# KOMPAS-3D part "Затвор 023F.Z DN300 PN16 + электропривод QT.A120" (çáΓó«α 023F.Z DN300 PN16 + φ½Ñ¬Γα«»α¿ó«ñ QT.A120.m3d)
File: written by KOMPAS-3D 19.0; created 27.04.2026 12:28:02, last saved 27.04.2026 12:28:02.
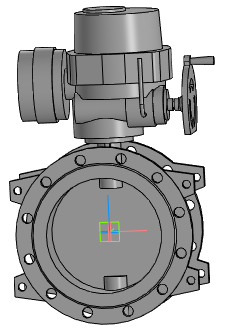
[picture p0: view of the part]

Document properties: Полное имя файла: Затвор 023F.Z DN300 PN16 + электропривод QT.A120.a3d

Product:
- Part/product: Затвор 023F.Z DN300 PN16 + электропривод QT.A120
    Масса: 223.118

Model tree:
1. Операция без истории:1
